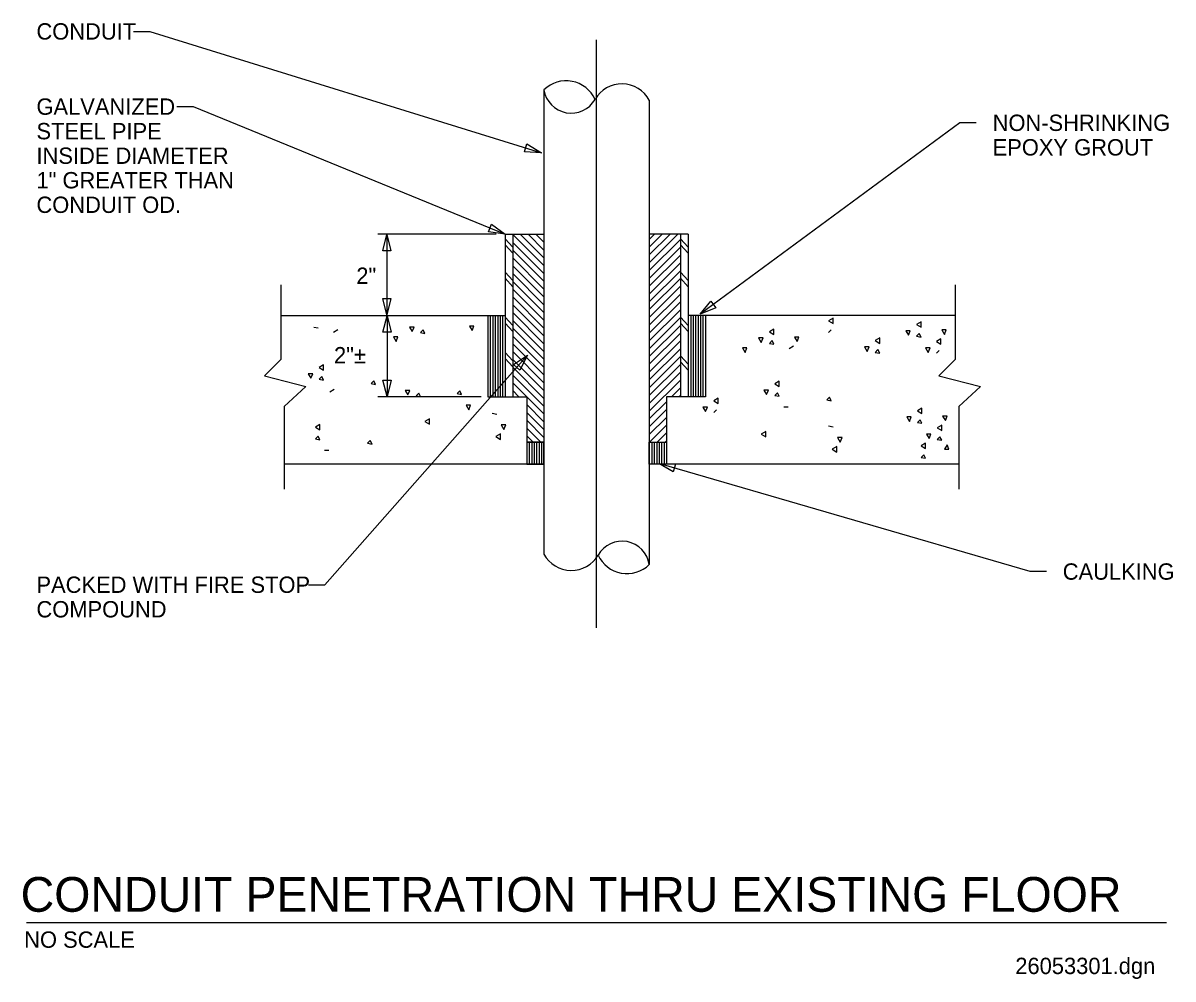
# Model space of a CAD drawing. Extents: x 10312.2 to 10359, y 10102.7 to 10141.7.
import ezdxf

# ---------------------------------------------------------------- set-up
doc = ezdxf.new("R2010")
doc.units = 0
for name, color, linetype in [('G-ANNO-TEXT', 7, 'Continuous'), ('Level 3', 7, 'Continuous'), ('Level 49', 7, 'Continuous'), ('Level 52', 7, 'Continuous'), ('Level 60', 7, 'Continuous'), ('Level 61', 7, 'Continuous'), ('Level 62', 7, 'Continuous'), ('Level 63', 7, 'Continuous')]:
    doc.layers.add(name, color=color, linetype=linetype)

msp = doc.modelspace()

# ---------------------------------------------------------------- linework, layer by layer
at = {"layer": 'Level 49'}
for p, q in [((10332.722, 10124.604), (10333.423, 10124.604)), ((10338.414, 10124.604), (10338.414, 10123.712))]:
    msp.add_line(p, q, dxfattribs=at)
at = {"layer": 'Level 52'}
msp.add_line((10312.352, 10105.032), (10358.784, 10105.032), dxfattribs=at)
at = {"layer": 'Level 60'}
for p, q in [((10332.154, 10132.555), (10331.839, 10132.896)), ((10332.154, 10133.067), (10333.423, 10131.798)), ((10332.154, 10132.748), (10333.423, 10131.48)), ((10332.459, 10133.08), (10333.423, 10132.116)), ((10332.777, 10133.08), (10333.423, 10132.434)), ((10333.096, 10133.08), (10333.423, 10132.752)), ((10333.414, 10133.08), (10333.423, 10133.071)), ((10337.713, 10132.868), (10337.925, 10133.08)), ((10337.713, 10132.55), (10338.243, 10133.08)), ((10337.713, 10132.232), (10338.561, 10133.08)), ((10337.713, 10131.914), (10338.879, 10133.08)), ((10337.713, 10131.595), (10338.982, 10132.864)), ((10339.297, 10132.555), (10338.982, 10132.896)), ((10332.154, 10132.306), (10331.839, 10132.647)), ((10332.154, 10132.43), (10333.423, 10131.161)), ((10337.713, 10131.277), (10338.982, 10132.546)), ((10337.713, 10130.959), (10338.982, 10132.228)), ((10339.297, 10132.306), (10338.982, 10132.647)), ((10332.154, 10132.112), (10333.423, 10130.843)), ((10332.154, 10131.794), (10333.423, 10130.525)), ((10337.713, 10130.641), (10338.982, 10131.91)), ((10332.154, 10131.189), (10331.839, 10131.53)), ((10332.154, 10130.941), (10331.839, 10131.282)), ((10332.154, 10131.476), (10333.423, 10130.207)), ((10337.713, 10130.323), (10338.982, 10131.591)), ((10337.713, 10130.004), (10338.982, 10131.273)), ((10339.297, 10131.189), (10338.982, 10131.53)), ((10339.297, 10130.941), (10338.982, 10131.282)), ((10332.154, 10131.157), (10333.423, 10129.889)), ((10332.154, 10130.839), (10333.423, 10129.571)), ((10337.713, 10129.686), (10338.982, 10130.955)), ((10332.154, 10130.521), (10333.423, 10129.252)), ((10337.713, 10129.368), (10338.982, 10130.637)), ((10332.154, 10130.203), (10333.423, 10128.934)), ((10332.154, 10129.885), (10333.423, 10128.616)), ((10337.713, 10129.05), (10338.982, 10130.319)), ((10337.713, 10128.732), (10338.982, 10130)), ((10332.154, 10129.358), (10331.839, 10129.699)), ((10332.154, 10129.11), (10331.839, 10129.451)), ((10332.154, 10129.566), (10333.423, 10128.298)), ((10337.713, 10128.413), (10338.982, 10129.682)), ((10339.297, 10129.358), (10338.982, 10129.699)), ((10339.297, 10129.11), (10338.982, 10129.451)), ((10345.2, 10129.656), (10345.017, 10129.546)), ((10345.017, 10129.546), (10345.2, 10129.436)), ((10345.2, 10129.436), (10345.2, 10129.656)), ((10348.784, 10129.509), (10348.601, 10129.399)), ((10348.601, 10129.399), (10348.784, 10129.29)), ((10348.784, 10129.29), (10348.784, 10129.509)), ((10324.043, 10129.294), (10324.226, 10129.258)), ((10325.031, 10129.184), (10324.848, 10129.075)), ((10327.95, 10129.293), (10328.059, 10129.11)), ((10328.132, 10129.293), (10327.95, 10129.293)), ((10328.059, 10129.11), (10328.132, 10129.293)), ((10328.498, 10129.183), (10328.388, 10129.073)), ((10328.388, 10129.073), (10328.571, 10129.037)), ((10328.571, 10129.037), (10328.498, 10129.183)), ((10330.567, 10129.332), (10330.385, 10129.332)), ((10330.385, 10129.332), (10330.494, 10129.149)), ((10330.494, 10129.149), (10330.567, 10129.332)), ((10332.154, 10129.248), (10333.423, 10127.98)), ((10332.154, 10128.93), (10333.423, 10127.661)), ((10337.713, 10128.095), (10338.982, 10129.364)), ((10337.713, 10127.777), (10338.982, 10129.046)), ((10342.786, 10129.216), (10342.603, 10129.107)), ((10342.603, 10129.107), (10342.786, 10128.997)), ((10342.786, 10128.997), (10342.786, 10129.216)), ((10345.127, 10129.18), (10345.017, 10129.07)), ((10348.345, 10129.143), (10348.162, 10129.143)), ((10348.162, 10129.143), (10348.272, 10128.96)), ((10348.272, 10128.96), (10348.345, 10129.143)), ((10348.711, 10129.034), (10348.601, 10128.924)), ((10348.784, 10128.887), (10348.711, 10129.034)), ((10349.808, 10129.18), (10349.625, 10129.18)), ((10349.625, 10129.18), (10349.735, 10128.997)), ((10349.735, 10128.997), (10349.808, 10129.18)), ((10327.474, 10128.89), (10327.291, 10128.89)), ((10327.291, 10128.89), (10327.401, 10128.707)), ((10327.401, 10128.707), (10327.474, 10128.89)), ((10332.154, 10128.612), (10333.423, 10127.343)), ((10337.713, 10127.459), (10338.982, 10128.728)), ((10342.347, 10128.851), (10342.164, 10128.851)), ((10342.164, 10128.851), (10342.274, 10128.668)), ((10342.274, 10128.668), (10342.347, 10128.851)), ((10342.713, 10128.741), (10342.603, 10128.631)), ((10342.603, 10128.631), (10342.786, 10128.594)), ((10342.786, 10128.594), (10342.713, 10128.741)), ((10343.59, 10128.521), (10343.408, 10128.411)), ((10343.81, 10128.887), (10343.627, 10128.887)), ((10343.627, 10128.887), (10343.737, 10128.704)), ((10343.737, 10128.704), (10343.81, 10128.887)), ((10346.663, 10128.485), (10346.48, 10128.485)), ((10346.48, 10128.485), (10346.589, 10128.302)), ((10346.589, 10128.302), (10346.663, 10128.485)), ((10347.102, 10128.851), (10346.919, 10128.741)), ((10346.919, 10128.741), (10347.102, 10128.631)), ((10347.102, 10128.631), (10347.102, 10128.851)), ((10348.601, 10128.924), (10348.784, 10128.887)), ((10349.589, 10128.814), (10349.406, 10128.704)), ((10349.406, 10128.704), (10349.589, 10128.594)), ((10349.589, 10128.594), (10349.589, 10128.814)), ((10332.154, 10127.922), (10331.839, 10128.263)), ((10332.154, 10127.674), (10331.839, 10128.015)), ((10332.154, 10128.294), (10333.423, 10127.025)), ((10337.713, 10127.141), (10338.982, 10128.409)), ((10337.713, 10126.822), (10338.982, 10128.091)), ((10339.297, 10127.781), (10338.982, 10128.122)), ((10341.506, 10128.448), (10341.615, 10128.265)), ((10341.689, 10128.448), (10341.506, 10128.448)), ((10341.615, 10128.265), (10341.689, 10128.448)), ((10347.028, 10128.375), (10346.919, 10128.265)), ((10346.919, 10128.265), (10347.102, 10128.228)), ((10347.102, 10128.228), (10347.028, 10128.375)), ((10348.967, 10128.448), (10349.077, 10128.265)), ((10349.15, 10128.448), (10348.967, 10128.448)), ((10349.077, 10128.265), (10349.15, 10128.448)), ((10349.515, 10128.338), (10349.406, 10128.228)), ((10324.445, 10127.757), (10324.263, 10127.647)), ((10324.263, 10127.647), (10324.445, 10127.538)), ((10324.445, 10127.538), (10324.445, 10127.757)), ((10332.154, 10127.975), (10333.423, 10126.707)), ((10332.154, 10127.657), (10333.423, 10126.389)), ((10337.713, 10126.504), (10338.982, 10127.773)), ((10339.297, 10127.533), (10338.982, 10127.874)), ((10323.824, 10127.391), (10323.933, 10127.208)), ((10324.006, 10127.391), (10323.824, 10127.391)), ((10323.933, 10127.208), (10324.006, 10127.391)), ((10324.372, 10127.282), (10324.263, 10127.172)), ((10324.263, 10127.172), (10324.445, 10127.135)), ((10324.445, 10127.135), (10324.372, 10127.282)), ((10326.494, 10127.099), (10326.384, 10126.989)), ((10326.567, 10126.952), (10326.494, 10127.099)), ((10332.154, 10127.339), (10333.423, 10126.07)), ((10337.713, 10126.186), (10338.982, 10127.455)), ((10337.713, 10125.868), (10338.982, 10127.137)), ((10343.005, 10127.094), (10342.822, 10126.984)), ((10343.005, 10126.874), (10343.005, 10127.094)), ((10324.883, 10126.753), (10324.7, 10126.643)), ((10326.384, 10126.989), (10326.567, 10126.952)), ((10327.773, 10126.716), (10327.882, 10126.533)), ((10327.955, 10126.716), (10327.773, 10126.716)), ((10327.882, 10126.533), (10327.955, 10126.716)), ((10328.321, 10126.606), (10328.211, 10126.496)), ((10328.394, 10126.46), (10328.321, 10126.606)), ((10329.992, 10126.692), (10329.883, 10126.582)), ((10330.065, 10126.546), (10329.992, 10126.692)), ((10332.154, 10127.021), (10332.719, 10126.456)), ((10332.154, 10126.703), (10332.401, 10126.456)), ((10338.619, 10126.456), (10338.982, 10126.818)), ((10342.566, 10126.728), (10342.383, 10126.728)), ((10342.383, 10126.728), (10342.493, 10126.545)), ((10342.493, 10126.545), (10342.566, 10126.728)), ((10342.822, 10126.984), (10343.005, 10126.874)), ((10342.932, 10126.618), (10342.822, 10126.509)), ((10343.005, 10126.472), (10342.932, 10126.618)), ((10328.211, 10126.496), (10328.394, 10126.46)), ((10329.883, 10126.582), (10330.065, 10126.546)), ((10332.722, 10126.453), (10333.423, 10125.752)), ((10332.722, 10126.135), (10333.423, 10125.434)), ((10337.713, 10125.55), (10338.414, 10126.251)), ((10338.938, 10126.456), (10338.982, 10126.5)), ((10340.518, 10126.399), (10340.335, 10126.289)), ((10340.335, 10126.289), (10340.518, 10126.179)), ((10340.518, 10126.179), (10340.518, 10126.399)), ((10342.822, 10126.509), (10343.005, 10126.472)), ((10345.053, 10126.435), (10344.944, 10126.326)), ((10344.944, 10126.326), (10345.127, 10126.289)), ((10345.127, 10126.289), (10345.053, 10126.435)), ((10330.248, 10126.106), (10330.358, 10125.924)), ((10330.431, 10126.106), (10330.248, 10126.106)), ((10330.358, 10125.924), (10330.431, 10126.106)), ((10331.318, 10125.78), (10331.501, 10125.744)), ((10332.722, 10125.817), (10333.423, 10125.116)), ((10337.713, 10125.231), (10338.414, 10125.932)), ((10340.079, 10126.033), (10339.896, 10126.033)), ((10339.896, 10126.033), (10340.006, 10125.85)), ((10340.006, 10125.85), (10340.079, 10126.033)), ((10340.445, 10125.923), (10340.335, 10125.813)), ((10343.371, 10126.033), (10343.188, 10126.033)), ((10348.82, 10125.996), (10348.638, 10125.886)), ((10348.638, 10125.886), (10348.82, 10125.777)), ((10348.82, 10125.777), (10348.82, 10125.996)), ((10349.662, 10125.667), (10349.771, 10125.484)), ((10349.845, 10125.667), (10349.662, 10125.667)), ((10349.771, 10125.484), (10349.845, 10125.667)), ((10324.298, 10125.325), (10324.115, 10125.216)), ((10324.115, 10125.216), (10324.298, 10125.106)), ((10324.298, 10125.106), (10324.298, 10125.325)), ((10328.758, 10125.561), (10328.575, 10125.451)), ((10328.575, 10125.451), (10328.758, 10125.341)), ((10328.758, 10125.341), (10328.758, 10125.561)), ((10331.866, 10125.304), (10331.684, 10125.304)), ((10331.684, 10125.304), (10331.793, 10125.121)), ((10331.793, 10125.121), (10331.866, 10125.304)), ((10332.722, 10125.499), (10333.423, 10124.798)), ((10332.722, 10125.18), (10333.298, 10124.604)), ((10337.713, 10124.913), (10338.414, 10125.614)), ((10337.722, 10124.604), (10338.414, 10125.296)), ((10345.017, 10125.264), (10345.2, 10125.228)), ((10348.199, 10125.63), (10348.308, 10125.447)), ((10348.382, 10125.63), (10348.199, 10125.63)), ((10348.308, 10125.447), (10348.382, 10125.63)), ((10348.747, 10125.52), (10348.638, 10125.411)), ((10348.638, 10125.411), (10348.82, 10125.374)), ((10348.82, 10125.374), (10348.747, 10125.52)), ((10349.625, 10125.301), (10349.442, 10125.191)), ((10349.442, 10125.191), (10349.625, 10125.081)), ((10349.625, 10125.081), (10349.625, 10125.301)), ((10324.225, 10124.85), (10324.115, 10124.74)), ((10324.115, 10124.74), (10324.298, 10124.703)), ((10324.298, 10124.703), (10324.225, 10124.85)), ((10331.647, 10124.938), (10331.464, 10124.829)), ((10331.464, 10124.829), (10331.647, 10124.719)), ((10331.647, 10124.719), (10331.647, 10124.938)), ((10332.722, 10124.862), (10332.98, 10124.604)), ((10338.04, 10124.604), (10338.414, 10124.978)), ((10342.457, 10125.045), (10342.274, 10124.935)), ((10342.274, 10124.935), (10342.457, 10124.825)), ((10342.457, 10124.825), (10342.457, 10125.045)), ((10345.383, 10124.789), (10345.492, 10124.606)), ((10345.565, 10124.789), (10345.383, 10124.789)), ((10345.492, 10124.606), (10345.565, 10124.789)), ((10349.186, 10124.935), (10349.003, 10124.935)), ((10349.003, 10124.935), (10349.113, 10124.752)), ((10349.113, 10124.752), (10349.186, 10124.935)), ((10349.552, 10124.825), (10349.442, 10124.715)), ((10349.442, 10124.715), (10349.625, 10124.679)), ((10349.625, 10124.679), (10349.552, 10124.825)), ((10324.664, 10124.264), (10324.481, 10124.264)), ((10326.346, 10124.667), (10326.237, 10124.557)), ((10326.237, 10124.557), (10326.419, 10124.52)), ((10326.419, 10124.52), (10326.346, 10124.667)), ((10338.359, 10124.604), (10338.414, 10124.66)), ((10345.346, 10124.423), (10345.163, 10124.313)), ((10345.163, 10124.313), (10345.346, 10124.203)), ((10345.346, 10124.203), (10345.346, 10124.423)), ((10348.967, 10124.569), (10348.784, 10124.459)), ((10348.784, 10124.459), (10348.967, 10124.349)), ((10348.967, 10124.349), (10348.967, 10124.569)), ((10349.845, 10124.496), (10349.735, 10124.313)), ((10349.735, 10124.313), (10349.918, 10124.313)), ((10349.918, 10124.313), (10349.845, 10124.496)), ((10348.894, 10124.093), (10348.784, 10123.984)), ((10348.784, 10123.984), (10348.967, 10123.947)), ((10348.967, 10123.947), (10348.894, 10124.093))]:
    msp.add_line(p, q, dxfattribs=at)
at = {"layer": 'Level 61'}
for p, q in [((10322.704, 10129.768), (10331.839, 10129.768)), ((10331.138, 10129.768), (10331.138, 10126.456)), ((10331.238, 10129.768), (10331.238, 10126.456)), ((10331.338, 10129.768), (10331.338, 10126.456)), ((10331.438, 10129.768), (10331.438, 10126.456)), ((10331.538, 10129.768), (10331.538, 10126.456)), ((10331.638, 10129.768), (10331.638, 10126.456)), ((10331.738, 10129.768), (10331.738, 10126.456)), ((10350.176, 10129.768), (10339.297, 10129.768)), ((10339.398, 10129.768), (10339.398, 10126.456)), ((10339.498, 10129.768), (10339.498, 10126.456)), ((10339.598, 10129.768), (10339.598, 10126.456)), ((10339.698, 10129.768), (10339.698, 10126.456)), ((10339.798, 10129.768), (10339.798, 10126.456)), ((10339.898, 10129.768), (10339.898, 10126.456)), ((10339.998, 10129.768), (10339.998, 10126.456)), ((10331.138, 10126.456), (10331.839, 10126.456)), ((10332.722, 10126.456), (10332.722, 10124.604)), ((10338.414, 10126.456), (10338.414, 10124.604)), ((10339.998, 10126.456), (10339.297, 10126.456)), ((10332.722, 10124.604), (10332.722, 10123.712)), ((10332.822, 10124.604), (10332.822, 10123.712)), ((10332.922, 10124.604), (10332.922, 10123.712)), ((10333.022, 10124.604), (10333.022, 10123.712)), ((10333.122, 10124.604), (10333.122, 10123.712)), ((10333.222, 10124.604), (10333.222, 10123.712)), ((10333.322, 10124.604), (10333.322, 10123.712)), ((10337.814, 10124.604), (10337.814, 10123.712)), ((10337.914, 10124.604), (10337.914, 10123.712)), ((10338.014, 10124.604), (10338.014, 10123.712)), ((10338.114, 10124.604), (10338.114, 10123.712)), ((10338.214, 10124.604), (10338.214, 10123.712)), ((10338.314, 10124.604), (10338.314, 10123.712)), ((10333.423, 10123.712), (10322.843, 10123.712)), ((10350.315, 10123.712), (10337.713, 10123.712))]:
    msp.add_line(p, q, dxfattribs=at)
for points in [[(10332.722, 10123.712), (10333.423, 10123.712), (10333.423, 10124.604), (10332.722, 10124.604)], [(10338.414, 10123.712), (10337.713, 10123.712), (10337.713, 10124.604), (10338.414, 10124.604)]]:
    msp.add_lwpolyline(points, close=True, dxfattribs=at)
at = {"layer": 'Level 62'}
for p, q in [((10333.423, 10138.96), (10333.423, 10120.039)), ((10337.713, 10138.539), (10337.713, 10119.619)), ((10331.839, 10133.08), (10333.423, 10133.08)), ((10331.839, 10133.08), (10331.839, 10126.456)), ((10332.154, 10133.08), (10332.154, 10126.456)), ((10339.297, 10133.08), (10337.713, 10133.08)), ((10338.982, 10133.08), (10338.982, 10126.456)), ((10339.297, 10133.08), (10339.297, 10126.456)), ((10331.839, 10126.456), (10332.722, 10126.456)), ((10339.297, 10126.456), (10338.414, 10126.456))]:
    msp.add_line(p, q, dxfattribs=at)
for centre, radius, start, end in [((10334.329, 10138.036), 1.294, 24.5828, 134.427), ((10334.532, 10139.133), 1.122, 188.8535, 330.1563), ((10336.599, 10137.943), 1.263, 28.1692, 150.0111), ((10336.604, 10119.446), 1.122, 8.8535, 150.1563), ((10334.537, 10120.636), 1.263, 208.1692, 330.0111), ((10336.807, 10120.542), 1.294, 204.5828, 314.427)]:
    msp.add_arc(centre, radius, start, end, dxfattribs=at)
at = {"layer": 'Level 63'}
for p, q in [((10316.704, 10141.344), (10317.37, 10141.344)), ((10317.37, 10141.344), (10333.317, 10136.402)), ((10335.568, 10117.036), (10335.568, 10141.005)), ((10318.466, 10138.279), (10319.133, 10138.279)), ((10319.133, 10138.279), (10331.839, 10133.08)), ((10350.364, 10137.62), (10339.785, 10129.818)), ((10351.031, 10137.62), (10350.364, 10137.62)), ((10331.469, 10133.08), (10326.653, 10133.08)), ((10327.023, 10133.073), (10327.023, 10129.797)), ((10322.704, 10131.02), (10322.704, 10127.972)), ((10350.176, 10131.02), (10350.176, 10127.972)), ((10327.031, 10129.748), (10327.031, 10126.463)), ((10324.494, 10118.794), (10332.749, 10128.156)), ((10322.704, 10127.972), (10322.033, 10127.309)), ((10350.176, 10127.972), (10349.505, 10127.309)), ((10322.033, 10127.309), (10323.727, 10126.867)), ((10349.505, 10127.309), (10351.199, 10126.867)), ((10323.727, 10126.867), (10322.843, 10126.056)), ((10351.199, 10126.867), (10350.315, 10126.056)), ((10330.87, 10126.456), (10326.653, 10126.456)), ((10322.843, 10126.056), (10322.843, 10122.682)), ((10350.315, 10126.056), (10350.315, 10122.682)), ((10353.22, 10119.331), (10338.097, 10123.74)), ((10353.886, 10119.331), (10353.22, 10119.331)), ((10323.827, 10118.794), (10324.494, 10118.794))]:
    msp.add_line(p, q, dxfattribs=at)
for points in [[(10332.729, 10136.759), (10333.317, 10136.402), (10332.631, 10136.441)], [(10331.285, 10133.487), (10331.839, 10133.08), (10331.159, 10133.178)], [(10326.856, 10132.407), (10327.023, 10133.073), (10327.189, 10132.407)], [(10327.189, 10130.464), (10327.023, 10129.797), (10326.856, 10130.464)], [(10340.42, 10130.08), (10339.785, 10129.818), (10340.222, 10130.348)], [(10326.865, 10129.081), (10327.031, 10129.748), (10327.198, 10129.081)], [(10332.183, 10127.766), (10332.749, 10128.156), (10332.433, 10127.545)], [(10327.198, 10127.13), (10327.031, 10126.463), (10326.865, 10127.13)], [(10338.691, 10123.394), (10338.097, 10123.74), (10338.784, 10123.714)]]:
    msp.add_lwpolyline(points, close=True, dxfattribs=at)

# ---------------------------------------------------------------- texts
at = {"layer": 'G-ANNO-TEXT'}
msp.add_text('2"±', height=0.6667, dxfattribs=at).set_placement((10324.87, 10127.814))
at = {"layer": 'Level 3'}
msp.add_text('26053301.dgn', height=0.66667, dxfattribs=at).set_placement((10352.62, 10102.926))
at = {"layer": 'Level 52'}
for s, height, p in [('CONDUIT PENETRATION THRU EXISTING FLOOR', 1.41667, (10312.107, 10105.465)), ('NO SCALE', 0.6667, (10312.251, 10103.997))]:
    msp.add_text(s, height=height, dxfattribs=at).set_placement(p)
at = {"layer": 'Level 63'}
for s, height, p in [('CONDUIT', 0.6667, (10312.751, 10141.011)), ('GALVANIZED ', 0.66667, (10312.751, 10137.946)), ('NON-SHRINKING', 0.66667, (10351.697, 10137.287)), ('STEEL PIPE', 0.6667, (10312.751, 10136.946)), ('EPOXY GROUT', 0.66667, (10351.697, 10136.287)), ('INSIDE DIAMETER', 0.66667, (10312.751, 10135.946)), ('1" GREATER THAN', 0.66667, (10312.751, 10134.946)), ('CONDUIT OD.', 0.66667, (10312.751, 10133.946)), ('2"', 0.6667, (10325.779, 10131.053)), ('CAULKING', 0.6667, (10354.553, 10118.998)), ('PACKED WITH FIRE STOP', 0.66667, (10312.751, 10118.461)), ('COMPOUND', 0.6667, (10312.751, 10117.461))]:
    msp.add_text(s, height=height, dxfattribs=at).set_placement(p)

doc.saveas('drawing.dxf')
